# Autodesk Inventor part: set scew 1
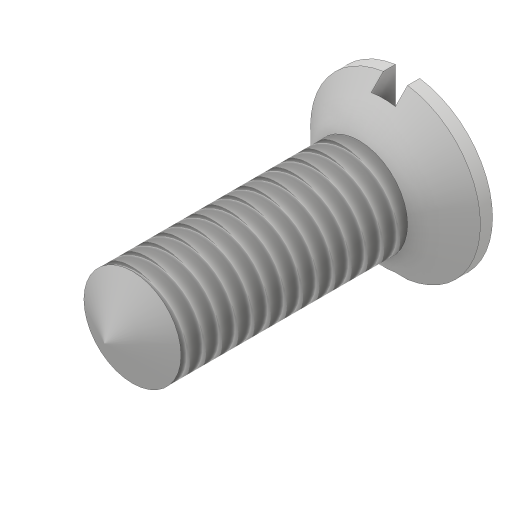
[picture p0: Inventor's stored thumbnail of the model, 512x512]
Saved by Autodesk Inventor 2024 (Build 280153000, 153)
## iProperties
Created: 2016-06
Part Number: set scew 1
Material: Generic
Document SubType Name: Modeling
Designer: CADCIM
Density: 1 g/cm^3
Appearance: Default
Mass: 0.577668 g
Surface Area: 5.12671 cm^2
Volume: 0.577668 cm^3
Author: CADCIM
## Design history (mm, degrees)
sketch "Sketch1"
  geometry: C1 r 3 at (0, 0); 1 further point
  constraints: 1 centre point, 1 coincident
  dimensions: "d0" = 6 diameter of C1
extrude "Extrusion1" new body sketch "Sketch1" distance "d1" = 14; taper "d2" = 0 deg
revolve "Revolution1" stored, may be unused: angle "d7" = 90 deg
sketch "Sketch3"
  geometry: C1 r 5.25 at (0, 0); 1 further point
  constraints: 1 centre point, 1 coincident
  dimensions: "d8" = 10.5 diameter of C1
extrude "Extrusion2" sketch "Sketch3" distance "d9" = 26.75; taper "d10" = 0 deg
sketch "Sketch4"
  geometry: L1 (-0.75, 8.347)-(0.75, 8.347); L2 (0.75, 8.347)-(0.75, -8.125); L3 (0.75, -8.125)-(-0.75, -8.125); L4 (-0.75, -8.125)-(-0.75, 8.347); L5 (0, 0)-(0, 6.165)
  constraints: 10 end point, 3 parallel, 1 horizontal, 1 perpendicular, 1 other
  dimensions: "d11" = 1.5 distance of L1.start L1.end
extrude "Extrusion3" cut sketch "Sketch4" distance "d12" = 1.5; taper "d13" = 0 deg
thread "Thread2" dims "d19" = 10, "d20" = 0
revolve "Revolution3" stored, may be unused: angle "d23" = 90 deg
body "Solid1"
sketch "Sketch5"
  geometry: L1 (0, 0)-(0, 3); L2 (0, 3)-(-1.732, 0); L3 (-1.732, 0)-(0, 0); L4 (0, 3)-(0, -3) reference; 1 further point
  constraints: 6 end point, 2 midpoint, 1 perpendicular, 1 point on line, 1 vertical
  dimensions: "d21" = 60 deg angle of L2 L3; "d22" = 3 distance of L1.start L1.end
sketch "Sketch2"
  geometry: L1 (14, -3)-(14, 3) reference; L2 (14, 0)-(14, -3); L3 (14, -3)-(17, -6); L4 (17, -6)-(17, 0); L5 (17, 0)-(14, 0); 1 further point
  constraints: 8 end point, 2 vertical, 1 midpoint, 1 perpendicular
  dimensions: "d4" = 3 distance of L2.start L2.end; "d5" = 6 distance of L4.end L3.end; "d6" = 3 distance from line of L1.start L4
